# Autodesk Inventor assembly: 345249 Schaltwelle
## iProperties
Company: Mayer & Müller AG
Created: 2006-03
Part Number: 345249 Schaltwelle
Document SubType Name: Assembly
Designer: I.Baliuc
Description: Schaltwelle, kompl.
Cost Center: 0,701 kg
Authority: 155658 mm^3
Mass: 697.752 g
Surface Area: 509.347 cm^2
Volume: 155.244 cm^3
Density: 4.49455 g/cm^3
Zweck: für DC Vorkontakt
SaveDate: 2006-10-25
SaveTime: 23:26
TotalMass: 0,701 kg
TotalVolume: 155658 mm^3
Author: T.Messerschmitt
Revision Number: 345249
